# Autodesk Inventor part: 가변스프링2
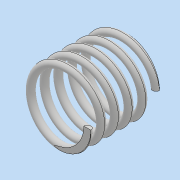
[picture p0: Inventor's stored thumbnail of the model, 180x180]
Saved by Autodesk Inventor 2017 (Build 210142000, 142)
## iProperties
Part Number: 가변스프링2
Material: 일반
Document SubType Name: Modeling
Designer: MRC
Density: 1 g/cm^3
Appearance: 기본값
Author: MRC
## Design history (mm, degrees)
sketch "스케치1"
  geometry: L1 (0, 0)-(0, 19.5); L2 (0, 19.5)-(9, 19.5); L3 (0, 0)-(9, 0); C1 r 1 at (9, 0)
  constraints: 6 end point, 2 horizontal, 1 centre point, 1 coincident, 1 vertical
  dimensions: "d0" = 19.5 distance of L1.start L1.end (derived); "d1" = 9 distance of L1.end L2.end; "d2" = 9 distance of L1.start L3.end; "d3" = 2 diameter of C1
feature "코일1" sketch "스케치1" pitch "d4" = 10; turns "d6" = 5; dims "d5" = 19.5 (= d0), "d7" = 0, angle "d8" = 90 deg, angle "d9" = 90 deg, "d10" = 0, "d11" = 0
sketch "스케치2"
  geometry: L1 (19.5, 21.748)-(0, 21.748); L2 (0, 21.748)-(0, -21.748); L3 (0, -21.748)-(19.5, -21.748); L4 (19.5, -21.748)-(19.5, 21.748); 2 further points
  constraints: 8 end point, 2 midpoint, 2 parallel, 1 coincident, 1 horizontal, 1 perpendicular
  dimensions: "d12" = 19.5 distance of L2.end L3.end (= d0); "d13" = 43.49633 distance of L3.end L1.start
extrude "돌출1" sketch "스케치2" stored distance "d14" = 0; taper "d15" = 0 deg
node "솔리드1"
